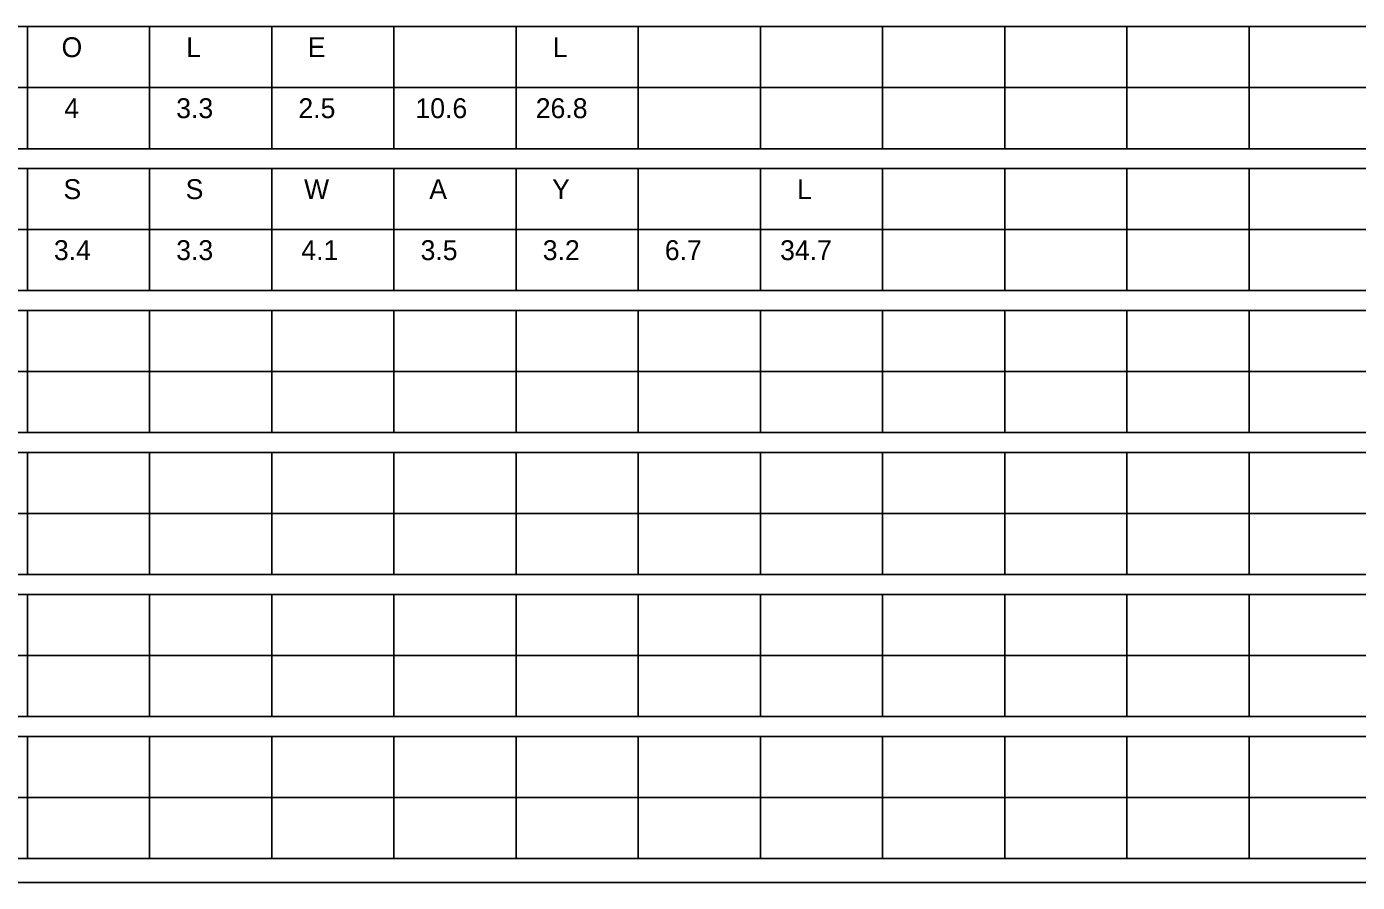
# Model space of a CAD drawing. Extents: x 17890587 to 17890754, y 17897693 to 17897992.
# Drawn here: x 17890595.51 to 17890605.35, y 17897889.79 to 17897896.11 of the extents above; entities that cross this region are included whole.
import ezdxf

# ---------------------------------------------------------------- set-up
doc = ezdxf.new("R2010")
doc.units = 0
doc.layers.add('GSSign', color=7, linetype='Continuous')
doc.layers.add('SheetLinesMisc2_dp', color=7, linetype='Continuous')

msp = doc.modelspace()

# ---------------------------------------------------------------- linework, layer by layer
at = {"layer": 'SheetLinesMisc2_dp'}
for p, q in [((17890588.6701, 17897896.115), (17890610.866, 17897896.115)), ((17890595.5165, 17897896.115), (17890595.5165, 17897895.2131)), ((17890596.4193, 17897896.115), (17890596.4193, 17897895.2131)), ((17890597.3221, 17897896.115), (17890597.3221, 17897895.2131)), ((17890598.225, 17897896.115), (17890598.225, 17897895.2131)), ((17890599.1281, 17897896.115), (17890599.1281, 17897895.2131)), ((17890600.031, 17897896.115), (17890600.031, 17897895.2131)), ((17890600.9338, 17897896.115), (17890600.9338, 17897895.2131)), ((17890601.8367, 17897896.115), (17890601.8367, 17897895.2131)), ((17890602.7398, 17897896.115), (17890602.7398, 17897895.2131)), ((17890603.6426, 17897896.115), (17890603.6426, 17897895.2131)), ((17890604.5455, 17897896.115), (17890604.5455, 17897895.2131)), ((17890588.6701, 17897895.6641), (17890610.866, 17897895.6641)), ((17890588.6701, 17897895.2131), (17890610.866, 17897895.2131)), ((17890588.6701, 17897895.0661), (17890610.866, 17897895.0661)), ((17890595.5165, 17897895.0661), (17890595.5165, 17897894.1645)), ((17890596.4193, 17897895.0661), (17890596.4193, 17897894.1645)), ((17890597.3221, 17897895.0661), (17890597.3221, 17897894.1645)), ((17890598.225, 17897895.0661), (17890598.225, 17897894.1645)), ((17890599.1281, 17897895.0661), (17890599.1281, 17897894.1645)), ((17890600.031, 17897895.0661), (17890600.031, 17897894.1645)), ((17890600.9338, 17897895.0661), (17890600.9338, 17897894.1645)), ((17890601.8367, 17897895.0661), (17890601.8367, 17897894.1645)), ((17890602.7398, 17897895.0661), (17890602.7398, 17897894.1645)), ((17890603.6426, 17897895.0661), (17890603.6426, 17897894.1645)), ((17890604.5455, 17897895.0661), (17890604.5455, 17897894.1645)), ((17890588.6701, 17897894.6151), (17890610.866, 17897894.6153)), ((17890588.6701, 17897894.1645), (17890610.866, 17897894.1645)), ((17890588.6701, 17897894.0174), (17890610.866, 17897894.0174)), ((17890595.5165, 17897894.0174), (17890595.5165, 17897893.1157)), ((17890596.4193, 17897894.0174), (17890596.4193, 17897893.1157)), ((17890597.3221, 17897894.0174), (17890597.3221, 17897893.1157)), ((17890598.225, 17897894.0174), (17890598.225, 17897893.1157)), ((17890599.1281, 17897894.0174), (17890599.1281, 17897893.1157)), ((17890600.031, 17897894.0174), (17890600.031, 17897893.1157)), ((17890600.9338, 17897894.0174), (17890600.9338, 17897893.1157)), ((17890601.8367, 17897894.0174), (17890601.8367, 17897893.1157)), ((17890602.7398, 17897894.0174), (17890602.7398, 17897893.1157)), ((17890603.6426, 17897894.0174), (17890603.6426, 17897893.1157)), ((17890604.5455, 17897894.0174), (17890604.5455, 17897893.1157)), ((17890588.6701, 17897893.5664), (17890610.866, 17897893.5664)), ((17890588.6701, 17897893.1157), (17890610.866, 17897893.1157)), ((17890588.6701, 17897892.9687), (17890610.866, 17897892.9687)), ((17890595.5165, 17897892.9687), (17890595.5165, 17897892.0668)), ((17890596.4193, 17897892.9687), (17890596.4193, 17897892.0668)), ((17890597.3221, 17897892.9687), (17890597.3221, 17897892.0668)), ((17890598.225, 17897892.9687), (17890598.225, 17897892.0668)), ((17890599.1281, 17897892.9687), (17890599.1281, 17897892.0668)), ((17890600.031, 17897892.9687), (17890600.031, 17897892.0668)), ((17890600.9338, 17897892.9687), (17890600.9338, 17897892.0668)), ((17890601.8367, 17897892.9687), (17890601.8367, 17897892.0668)), ((17890602.7398, 17897892.9687), (17890602.7398, 17897892.0668)), ((17890603.6426, 17897892.9687), (17890603.6426, 17897892.0668)), ((17890604.5455, 17897892.9687), (17890604.5455, 17897892.0668)), ((17890588.6701, 17897892.5177), (17890610.866, 17897892.5177)), ((17890588.6701, 17897892.0668), (17890610.866, 17897892.0668)), ((17890588.6701, 17897891.9198), (17890610.866, 17897891.9198)), ((17890595.5165, 17897891.9198), (17890595.5165, 17897891.0181)), ((17890596.4193, 17897891.9198), (17890596.4193, 17897891.0181)), ((17890597.3221, 17897891.9198), (17890597.3221, 17897891.0181)), ((17890598.225, 17897891.9198), (17890598.225, 17897891.0181)), ((17890599.1281, 17897891.9198), (17890599.1281, 17897891.0181)), ((17890600.031, 17897891.9198), (17890600.031, 17897891.0181)), ((17890600.9338, 17897891.9198), (17890600.9338, 17897891.0181)), ((17890601.8367, 17897891.9198), (17890601.8367, 17897891.0181)), ((17890602.7398, 17897891.9198), (17890602.7398, 17897891.0181)), ((17890603.6426, 17897891.9198), (17890603.6426, 17897891.0181)), ((17890604.5455, 17897891.9198), (17890604.5455, 17897891.0181)), ((17890588.6701, 17897891.469), (17890610.866, 17897891.469)), ((17890588.6701, 17897891.0181), (17890610.866, 17897891.0181)), ((17890588.6701, 17897890.871), (17890610.866, 17897890.871)), ((17890595.5165, 17897890.871), (17890595.5165, 17897889.9694)), ((17890596.4193, 17897890.871), (17890596.4193, 17897889.9694)), ((17890597.3221, 17897890.871), (17890597.3221, 17897889.9694)), ((17890598.225, 17897890.871), (17890598.225, 17897889.9694)), ((17890599.1281, 17897890.871), (17890599.1281, 17897889.9694)), ((17890600.031, 17897890.871), (17890600.031, 17897889.9694)), ((17890600.9338, 17897890.871), (17890600.9338, 17897889.9694)), ((17890601.8367, 17897890.871), (17890601.8367, 17897889.9694)), ((17890602.7398, 17897890.871), (17890602.7398, 17897889.9694)), ((17890603.6426, 17897890.871), (17890603.6426, 17897889.9694)), ((17890604.5455, 17897890.871), (17890604.5455, 17897889.9694)), ((17890588.6701, 17897890.4204), (17890610.866, 17897890.4204)), ((17890588.6701, 17897889.9694), (17890610.866, 17897889.9694)), ((17890588.4536, 17897889.7923), (17890611.0193, 17897889.7923))]:
    msp.add_line(p, q, dxfattribs=at)

# ---------------------------------------------------------------- texts
at = {"layer": 'GSSign'}
for s, height, p in [('O', 0.147, (17890595.7683, 17897895.8895)), ('L', 0.147, (17890596.69, 17897895.8895)), ('E', 0.147, (17890597.5885, 17897895.8895)), ('L', 0.147, (17890599.3993, 17897895.8895)), ('3.3', 0.14705, (17890596.6157, 17897895.4387)), ('2.5', 0.14705, (17890597.5189, 17897895.4387)), ('10.6', 0.14705, (17890598.3841, 17897895.4387)), ('26.8', 0.14705, (17890599.2734, 17897895.4387)), ('4', 0.147, (17890595.7886, 17897895.4387)), ('S', 0.147, (17890595.7825, 17897894.8406)), ('S', 0.147, (17890596.6856, 17897894.8406)), ('W', 0.147, (17890597.5606, 17897894.8406)), ('A', 0.147, (17890598.4861, 17897894.8406)), ('Y', 0.147, (17890599.3943, 17897894.8406)), ('L', 0.147, (17890601.2055, 17897894.8406)), ('3.4', 0.14705, (17890595.7118, 17897894.3898)), ('3.3', 0.14705, (17890596.6157, 17897894.3898)), ('4.1', 0.14705, (17890597.5409, 17897894.3898)), ('3.5', 0.14705, (17890598.422, 17897894.3898)), ('3.2', 0.14705, (17890599.325, 17897894.3898)), ('6.7', 0.14705, (17890600.2275, 17897894.3898)), ('34.7', 0.14705, (17890601.0794, 17897894.3898))]:
    msp.add_text(s, height=height, dxfattribs=at).set_placement(p)

doc.saveas('drawing.dxf')
